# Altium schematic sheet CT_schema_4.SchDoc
size 368 x 243 mm
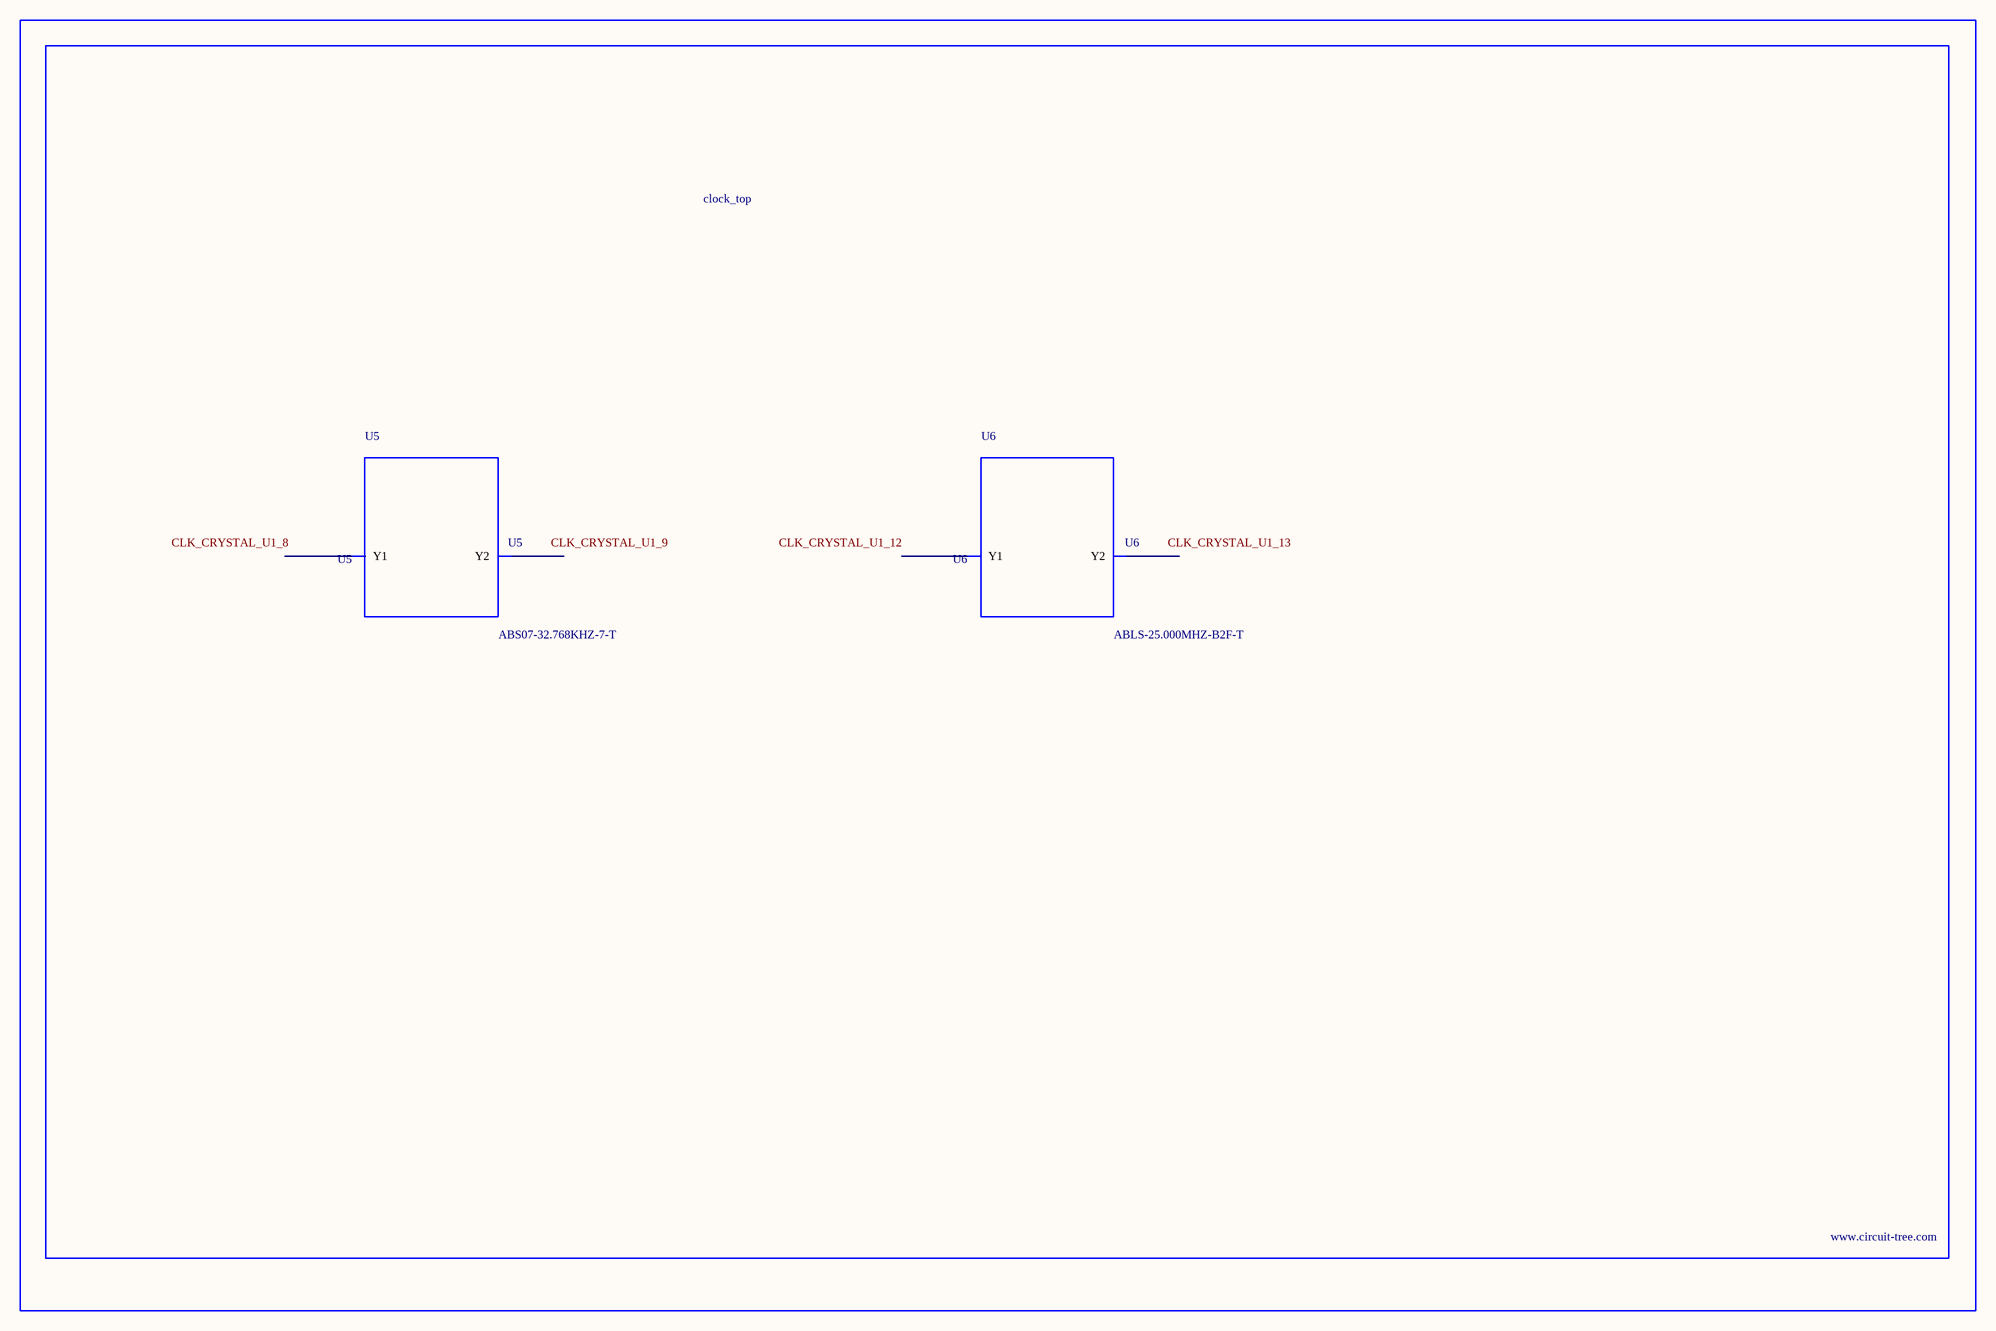
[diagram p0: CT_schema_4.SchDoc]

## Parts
BORDER3  (no value)
U5  ABS07-32.768KHZ-7-T  [ABS07-32.768KHZ-7-T]
U6  ABLS-25.000MHZ-B2F-T  [ABLS-25.000MHZ-B2F-T]

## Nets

Not connected (* = marked no-connect by the designer): U5 1(Y1) 2(Y2); U6 1(Y1) 2(Y2)

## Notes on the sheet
- Labels drawn without touching a wire or pin: CLK_CRYSTAL_U1_8, CLK_CRYSTAL_U1_9, CLK_CRYSTAL_U1_12, CLK_CRYSTAL_U1_13

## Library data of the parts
BORDER3 = BORDER_PAGE3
